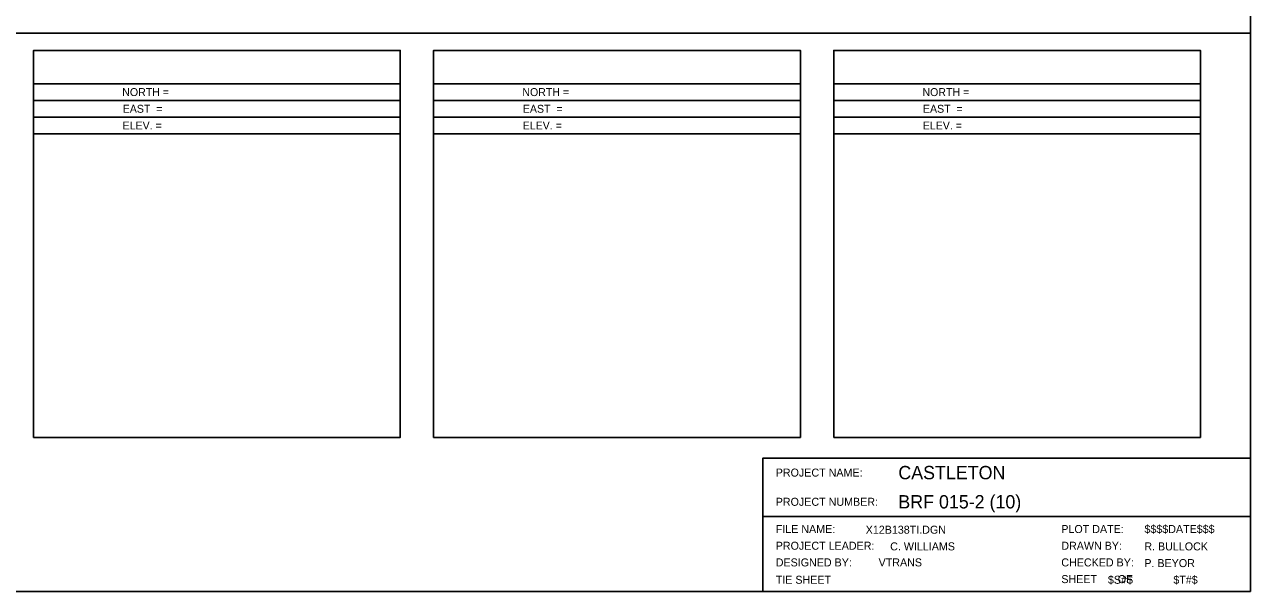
# Model space of a CAD drawing. Extents: x 1452748 to 1453388, y 402871 to 403291.
# Drawn here: x 1453020 to 1453387.7, y 402870.9 to 403040.8 of the extents above; entities that cross this region are included whole.
import ezdxf

# ---------------------------------------------------------------- set-up
doc = ezdxf.new("R2010")
doc.units = 0
doc.layers.add('NBL1', color=7, linetype='Continuous')
doc.layers.add('NBL2', color=7, linetype='Continuous')

msp = doc.modelspace()

# ---------------------------------------------------------------- linework, layer by layer
at = {"layer": 'NBL1'}
msp.add_line((1453241.42, 402893.39), (1453387.67, 402893.39), dxfattribs=at)
msp.add_lwpolyline([(1452747.67, 402870.89), (1453387.67, 402870.89), (1453387.67, 403290.89), (1452747.67, 403290.89)], close=True, dxfattribs=at)
msp.add_lwpolyline([(1453387.67, 402910.89), (1453241.42, 402910.89), (1453241.42, 402870.89)], dxfattribs=at)
at = {"layer": 'NBL2'}
for p, q in [((1452747.67, 403038.23), (1453387.67, 403038.23)), ((1453132.67, 403023.06), (1453022.67, 403023.06)), ((1453252.67, 403023.06), (1453142.67, 403023.06)), ((1453372.67, 403023.06), (1453262.67, 403023.06)), ((1453132.67, 403018.06), (1453022.67, 403018.06)), ((1453252.67, 403018.06), (1453142.67, 403018.06)), ((1453372.67, 403018.06), (1453262.67, 403018.06)), ((1453132.67, 403013.06), (1453022.67, 403013.06)), ((1453252.67, 403013.06), (1453142.67, 403013.06)), ((1453372.67, 403013.06), (1453262.67, 403013.06)), ((1453132.67, 403008.06), (1453022.67, 403008.06)), ((1453252.67, 403008.06), (1453142.67, 403008.06)), ((1453372.67, 403008.06), (1453262.67, 403008.06))]:
    msp.add_line(p, q, dxfattribs=at)
for points in [[(1453022.67, 402917.06), (1453132.67, 402917.06), (1453132.67, 403033.06), (1453022.67, 403033.06)], [(1453142.67, 402917.06), (1453252.67, 402917.06), (1453252.67, 403033.06), (1453142.67, 403033.06)], [(1453262.67, 402917.06), (1453372.67, 402917.06), (1453372.67, 403033.06), (1453262.67, 403033.06)]]:
    msp.add_lwpolyline(points, close=True, dxfattribs=at)

# ---------------------------------------------------------------- texts
at = {"layer": 'NBL1'}
for s, height, p in [('PROJECT NAME:', 2.4, (1453245.28, 402905.32)), ('CASTLETON                 ', 4, (1453282.05, 402904.52)), ('PROJECT NUMBER:', 2.4, (1453245.28, 402896.57)), ('BRF 015-2 (10)            ', 4, (1453282.05, 402895.77)), ('FILE NAME:', 2.4, (1453245.28, 402888.4)), ('      X12B138TI.DGN       ', 2.4, (1453266.91, 402888.2)), ('PLOT DATE:', 2.4, (1453330.93, 402888.4)), ('$$$$DATE$$$', 2.4, (1453355.86, 402888.4)), ('PROJECT LEADER:', 2.4, (1453245.28, 402883.4)), ('C. WILLIAMS         ', 2.4, (1453279.6, 402883.2)), ('DRAWN BY:', 2.4, (1453330.93, 402883.4)), ('R. BULLOCK   ', 2.4, (1453355.83, 402883.2)), ('DESIGNED BY:         VTRANS', 2.4, (1453245.28, 402878.4)), ('CHECKED BY:', 2.4, (1453330.93, 402878.4)), ('P. BEYOR     ', 2.4, (1453355.83, 402878.2)), ('TIE SHEET                         ', 2.4, (1453245.28, 402873.2)), ('SHEET       OF', 2.4, (1453330.93, 402873.4)), ('$S#$ ', 2.4, (1453344.91, 402873.2)), ('$T#$   ', 2.4, (1453364.53, 402873.2))]:
    msp.add_text(s, height=height, dxfattribs=at).set_placement(p)
at = {"layer": 'NBL2'}
for s, p in [('NORTH =             ', (1453049.28, 403019.37)), ('NORTH =             ', (1453169.28, 403019.37)), ('NORTH =             ', (1453289.28, 403019.37)), ('EAST  =             ', (1453049.43, 403014.37)), ('EAST  =             ', (1453169.43, 403014.37)), ('EAST  =             ', (1453289.43, 403014.37)), ('ELEV. =             ', (1453049.39, 403009.37)), ('ELEV. =             ', (1453169.39, 403009.37)), ('ELEV. =             ', (1453289.39, 403009.37))]:
    msp.add_text(s, height=2.375, dxfattribs=at).set_placement(p)

doc.saveas('drawing.dxf')
